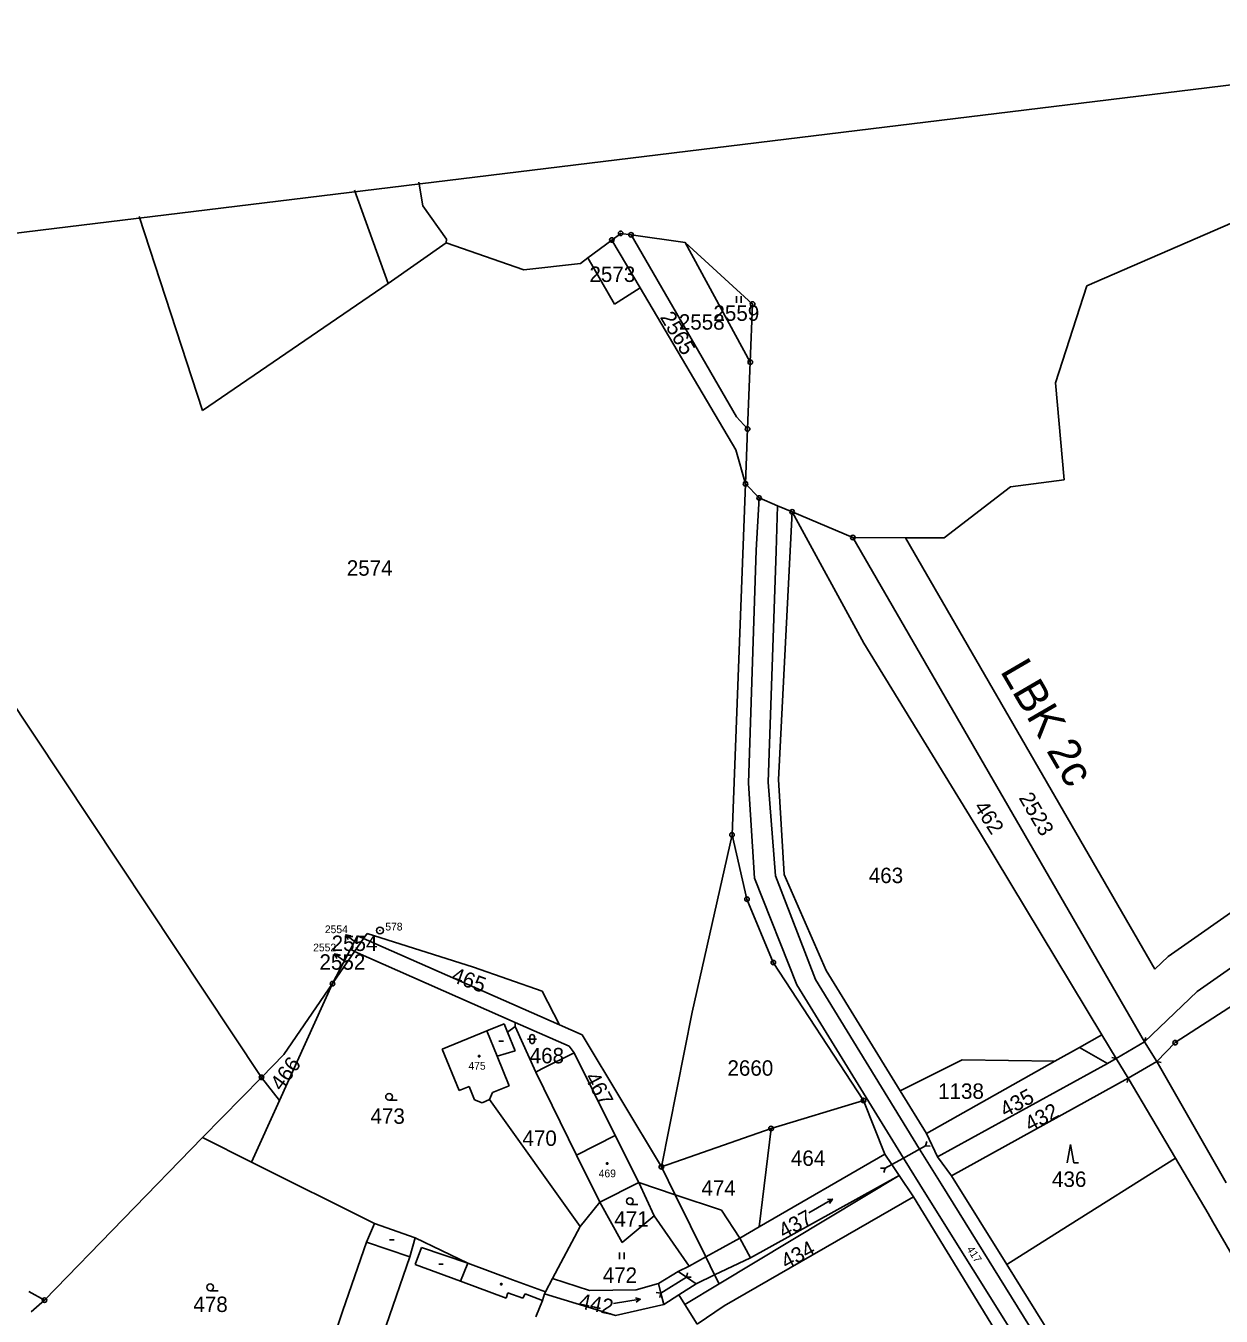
# Model space of a CAD drawing. Extents: x -567356 to -566716, y -1096092 to -1095603.
# Drawn here: x -567139.2 to -566875.4, y -1095888 to -1095603.4 of the extents above; entities that cross this region are included whole.
import ezdxf

# ---------------------------------------------------------------- set-up
doc = ezdxf.new("R2010")
doc.units = 0
for name, color, linetype in [('Vrstva 1', 7, 'Continuous'), ('Vrstva 13', 7, 'Continuous'), ('Vrstva 16', 7, 'Continuous'), ('Vrstva 17', 7, 'Continuous'), ('Vrstva 18', 7, 'Continuous'), ('Vrstva 19', 7, 'Continuous'), ('Vrstva 24', 7, 'Continuous'), ('Vrstva 25', 7, 'Continuous'), ('Vrstva 26', 7, 'Continuous'), ('Vrstva 4', 7, 'Continuous'), ('Vrstva 63', 7, 'Continuous')]:
    doc.layers.add(name, color=color, linetype=linetype)

msp = doc.modelspace()

# ---------------------------------------------------------------- linework, layer by layer
at = {"layer": 'Vrstva 1'}
for p, q in [((-567066.6, -1095639.66), (-567059.23, -1095660.29)), ((-567100.15, -1095688.25), (-567114.18, -1095645.47)), ((-567059.23, -1095660.29), (-567046.37, -1095651.29)), ((-567009.85, -1095650.68), (-567003.61, -1095661.22)), ((-567005.6, -1095649.54), (-566982.33, -1095689.66)), ((-566993.69, -1095651.22), (-566979.3, -1095677.61)), ((-567009.23, -1095664.84), (-567015.12, -1095654.61)), ((-567100.15, -1095688.25), (-567059.23, -1095660.29)), ((-567009.23, -1095664.84), (-567003.61, -1095661.22)), ((-567003.61, -1095661.22), (-566982.47, -1095696.92)), ((-566979.89, -1095692.34), (-566982.33, -1095689.66)), ((-566980.36, -1095704.46), (-566982.47, -1095696.92)), ((-566983.33, -1095781.86), (-566980.36, -1095704.46)), ((-566973.07, -1095769.68), (-566970.06, -1095710.63)), ((-566970.06, -1095710.63), (-566954.26, -1095739.57)), ((-566956.66, -1095716.28), (-566892.27, -1095827.53)), ((-566945.07, -1095716.34), (-566890.01, -1095811.47)), ((-566954.26, -1095739.57), (-566928.71, -1095781.18)), ((-567143.71, -1095750.26), (-567087.17, -1095835.34)), ((-566973.07, -1095769.68), (-566971.83, -1095790.57)), ((-566983.33, -1095781.86), (-566992.13, -1095820.96)), ((-566983.33, -1095781.86), (-566980.03, -1095796.03)), ((-566928.71, -1095781.18), (-566901.69, -1095825.95)), ((-566971.83, -1095790.57), (-566962.54, -1095811.81)), ((-566887.09, -1095808.66), (-566860.75, -1095790.2)), ((-566980.03, -1095796.03), (-566974.22, -1095810)), ((-566853.9, -1095797.61), (-566880.71, -1095816.4)), ((-567065.98, -1095804.1), (-567067.51, -1095807.04)), ((-567066.61, -1095807.58), (-567064.62, -1095804.7)), ((-567064.62, -1095804.7), (-567065.98, -1095804.1)), ((-567064.62, -1095804.7), (-567063.86, -1095803.59)), ((-567064.62, -1095804.7), (-567021.38, -1095823.77)), ((-567063.86, -1095803.59), (-567040.36, -1095811.06)), ((-567071.48, -1095814.67), (-567067.51, -1095807.04)), ((-567071.48, -1095814.67), (-567066.61, -1095807.58)), ((-567067.51, -1095807.04), (-567066.61, -1095807.58)), ((-567066.61, -1095807.58), (-567031.18, -1095823.21)), ((-566974.22, -1095810), (-566954.33, -1095840.45)), ((-566890.01, -1095811.47), (-566887.09, -1095808.66)), ((-567040.36, -1095811.06), (-567025.2, -1095816.33)), ((-566962.54, -1095811.81), (-566946.25, -1095838.28)), ((-567083.18, -1095840.45), (-567071.48, -1095814.67)), ((-567082.21, -1095830.27), (-567071.48, -1095814.67)), ((-567025.2, -1095816.33), (-567021.38, -1095823.77)), ((-566885.55, -1095827.69), (-566865.42, -1095814.66)), ((-566880.71, -1095816.4), (-566892.27, -1095827.53)), ((-566992.13, -1095820.96), (-566998.91, -1095855.06)), ((-567037.43, -1095825.1), (-567033.59, -1095823.53)), ((-567033.59, -1095823.53), (-567032.85, -1095825.38)), ((-567032.85, -1095825.38), (-567031.19, -1095824.09)), ((-567031.19, -1095824.09), (-567031.18, -1095823.21)), ((-567031.19, -1095824.09), (-567026.62, -1095834.18)), ((-567031.18, -1095823.21), (-567019.28, -1095828.45)), ((-567021.38, -1095823.77), (-567016.38, -1095825.97)), ((-567047.3, -1095829.12), (-567037.43, -1095825.1)), ((-567032.85, -1095825.38), (-567031.21, -1095829.51)), ((-567016.38, -1095825.97), (-566998.91, -1095855.06)), ((-566901.69, -1095825.95), (-566898.55, -1095831.15)), ((-566898.55, -1095831.15), (-566892.27, -1095827.53)), ((-566892.27, -1095827.53), (-566889.61, -1095831.87)), ((-566889.61, -1095831.87), (-566885.55, -1095827.69)), ((-567087.17, -1095835.34), (-567082.21, -1095830.27)), ((-567047.3, -1095829.12), (-567043.57, -1095838.27)), ((-567035.17, -1095830.65), (-567031.21, -1095829.51)), ((-567025.26, -1095833.48), (-567018.19, -1095829.96)), ((-567019.28, -1095828.45), (-567018.19, -1095829.96)), ((-567018.19, -1095829.96), (-567009.08, -1095848.19)), ((-566912.09, -1095831.8), (-566906.65, -1095828.74)), ((-566906.65, -1095828.74), (-566900.49, -1095832.28)), ((-567035.17, -1095830.65), (-567032.5, -1095837.19)), ((-566946.25, -1095838.28), (-566932.56, -1095831.46)), ((-566940.43, -1095847.73), (-566912.09, -1095831.8)), ((-566938, -1095852.89), (-566900.49, -1095832.28)), ((-566932.56, -1095831.46), (-566912.09, -1095831.8)), ((-566900.49, -1095832.28), (-566898.55, -1095831.15)), ((-566895.9, -1095835.52), (-566889.61, -1095831.87)), ((-566889.61, -1095831.87), (-566889.02, -1095832.89)), ((-566889.02, -1095832.89), (-566874.28, -1095858.61)), ((-567087.17, -1095835.34), (-567083.18, -1095840.45)), ((-567026.62, -1095834.18), (-567025.26, -1095833.48)), ((-567026.62, -1095834.18), (-567017.62, -1095852.49)), ((-566934.88, -1095857.04), (-566895.9, -1095835.52)), ((-566895.9, -1095835.52), (-566885.48, -1095853.18)), ((-567043.57, -1095838.27), (-567041.36, -1095837.37)), ((-567041.36, -1095837.37), (-567040.14, -1095840.32)), ((-567036.84, -1095840.26), (-567036.15, -1095838.68)), ((-567036.15, -1095838.68), (-567032.5, -1095837.19)), ((-566946.25, -1095838.28), (-566940.43, -1095847.73)), ((-567089.34, -1095854.03), (-567083.18, -1095840.45)), ((-567040.14, -1095840.32), (-567038.49, -1095840.93)), ((-567038.49, -1095840.93), (-567036.84, -1095840.26)), ((-567036.84, -1095840.26), (-567016.81, -1095868.27)), ((-566974.71, -1095846.61), (-566954.33, -1095840.45)), ((-566954.33, -1095840.45), (-566949.63, -1095852.31)), ((-566998.91, -1095855.06), (-566974.71, -1095846.61)), ((-566977.35, -1095868.33), (-566974.71, -1095846.61)), ((-567135.05, -1095884.49), (-567100.18, -1095848.6)), ((-567100.18, -1095848.6), (-567089.34, -1095854.03)), ((-567009.08, -1095848.19), (-567003.91, -1095858.56)), ((-566940.43, -1095847.73), (-566938, -1095852.89)), ((-567017.62, -1095852.49), (-567012.49, -1095862.9)), ((-566977.35, -1095868.33), (-566949.63, -1095852.31)), ((-566949.63, -1095852.31), (-566948.07, -1095854.58)), ((-566938, -1095852.89), (-566934.88, -1095857.04)), ((-566910.71, -1095869.05), (-566885.48, -1095853.18)), ((-566885.48, -1095853.18), (-566878.27, -1095865.39)), ((-567089.34, -1095854.03), (-567062.24, -1095867.59)), ((-566998.91, -1095855.06), (-566995.87, -1095861.24)), ((-566948.07, -1095854.58), (-566946.44, -1095856.96)), ((-567012.49, -1095862.9), (-567003.91, -1095858.56)), ((-567003.91, -1095858.56), (-567000.49, -1095865.9)), ((-566986.19, -1095880.91), (-566946.44, -1095856.96)), ((-566946.44, -1095856.96), (-566943.29, -1095861.67)), ((-566934.88, -1095857.04), (-566922.69, -1095876.58)), ((-566995.87, -1095861.24), (-566989.12, -1095874.96)), ((-566985.06, -1095885.7), (-566943.29, -1095861.67)), ((-566943.29, -1095861.67), (-566884.03, -1095958.24)), ((-567016.81, -1095868.27), (-567012.49, -1095862.9)), ((-567012.49, -1095862.9), (-567007.55, -1095871.78)), ((-567063.98, -1095871.66), (-567062.24, -1095867.59)), ((-567062.24, -1095867.59), (-567053.28, -1095870.73)), ((-567007.55, -1095871.78), (-567000.49, -1095865.9)), ((-567000.49, -1095865.9), (-566992.8, -1095877)), ((-566878.27, -1095865.39), (-566877.22, -1095867.21)), ((-566877.22, -1095867.21), (-566842.91, -1095926.64)), ((-567022.92, -1095879.69), (-567016.81, -1095868.27)), ((-566981.59, -1095870.78), (-566977.35, -1095868.33)), ((-566922.69, -1095876.58), (-566910.71, -1095869.05)), ((-567069.18, -1095886.79), (-567063.98, -1095871.66)), ((-567063.98, -1095871.66), (-567054.4, -1095874.96)), ((-567053.28, -1095870.73), (-567041.66, -1095876.31)), ((-566989.12, -1095874.96), (-566981.59, -1095870.78)), ((-567059.63, -1095890.09), (-567054.4, -1095874.96)), ((-566989.12, -1095874.96), (-566987.17, -1095878.92)), ((-567041.66, -1095876.31), (-567031.77, -1095880)), ((-566999.58, -1095880.79), (-566995.2, -1095878.17)), ((-566995.2, -1095878.17), (-566992.8, -1095877)), ((-566995.2, -1095878.17), (-566993.37, -1095879.4)), ((-566987.17, -1095878.92), (-566986.19, -1095880.91)), ((-566922.69, -1095876.58), (-566875.46, -1095952.32)), ((-567031.77, -1095880), (-567024.52, -1095882.64)), ((-567024.52, -1095882.64), (-567022.92, -1095879.69)), ((-567022.92, -1095879.69), (-567014.77, -1095882.35)), ((-567004.5, -1095882.17), (-566999.58, -1095880.79)), ((-566995.04, -1095883.32), (-566991.21, -1095880.86)), ((-566993.71, -1095885.45), (-566986.19, -1095880.91)), ((-566993.37, -1095879.4), (-566991.21, -1095880.86)), ((-567138.51, -1095882.55), (-567135.05, -1095884.49)), ((-567137.96, -1095887.08), (-567135.05, -1095884.49)), ((-567026.61, -1095888.14), (-567025.14, -1095884.52)), ((-567025.14, -1095884.52), (-567024.67, -1095883.12)), ((-567024.67, -1095883.12), (-567024.52, -1095882.64)), ((-567024.67, -1095883.12), (-567009.06, -1095887.89)), ((-567014.77, -1095882.35), (-567009.64, -1095882.27)), ((-567009.64, -1095882.27), (-567004.5, -1095882.17)), ((-566998.39, -1095885.47), (-566995.04, -1095883.32)), ((-566995.04, -1095883.32), (-566993.71, -1095885.45)), ((-567077.17, -1095910.04), (-567069.18, -1095886.79)), ((-567009.06, -1095887.89), (-566998.39, -1095885.47)), ((-566993.71, -1095885.45), (-566991.03, -1095889.76)), ((-566991.03, -1095889.76), (-566985.06, -1095885.7))]:
    msp.add_line(p, q, dxfattribs=at)
at = {"layer": 'Vrstva 13'}
for p, q in [((-566905.05, -1095660.75), (-566817.77, -1095622.91)), ((-567052.47, -1095637.93), (-567051.59, -1095643.13)), ((-567051.59, -1095643.13), (-567046.33, -1095650.51)), ((-567046.33, -1095650.51), (-567046.37, -1095651.29)), ((-567046.37, -1095651.29), (-567029.28, -1095657.25)), ((-567015.12, -1095654.61), (-567009.85, -1095650.68)), ((-567009.85, -1095650.68), (-567007.89, -1095649.21)), ((-567007.89, -1095649.21), (-567005.6, -1095649.54)), ((-567005.6, -1095649.54), (-566993.69, -1095651.22)), ((-566993.69, -1095651.22), (-566978.79, -1095664.8)), ((-567029.28, -1095657.25), (-567016.78, -1095655.85)), ((-567016.78, -1095655.85), (-567015.12, -1095654.61)), ((-566911.94, -1095682.15), (-566905.05, -1095660.75)), ((-566978.79, -1095664.8), (-566979.3, -1095677.61)), ((-566979.3, -1095677.61), (-566979.89, -1095692.34)), ((-566910.02, -1095703.54), (-566911.94, -1095682.15)), ((-566979.89, -1095692.34), (-566980.36, -1095704.46)), ((-566980.36, -1095704.46), (-566977.35, -1095707.56)), ((-566936.49, -1095716.38), (-566921.91, -1095705.12)), ((-566921.91, -1095705.12), (-566910.02, -1095703.54)), ((-566977.35, -1095707.56), (-566973.27, -1095709.28)), ((-566973.27, -1095709.28), (-566970.06, -1095710.63)), ((-566970.06, -1095710.63), (-566956.66, -1095716.28)), ((-566956.66, -1095716.28), (-566945.07, -1095716.34)), ((-566945.07, -1095716.34), (-566936.49, -1095716.38))]:
    msp.add_line(p, q, dxfattribs=at)
at = {"layer": 'Vrstva 16'}
for p, q in [((-567066.15, -1095805.71), (-567068.57, -1095803.94)), ((-567068.6, -1095809.9), (-567071.02, -1095808.13))]:
    msp.add_line(p, q, dxfattribs=at)
for points in [[(-567068.06, -1095804.94), (-567068.57, -1095803.94), (-567067.47, -1095804.13)], [(-567070.51, -1095809.13), (-567071.02, -1095808.13), (-567069.92, -1095808.32)]]:
    msp.add_lwpolyline(points, dxfattribs=at)
at = {"layer": 'Vrstva 24'}
for centre, radius in [((-567009.85, -1095650.68), 0.5), ((-567009.85, -1095650.68), 0.0327), ((-567007.89, -1095649.21), 0.5), ((-567007.89, -1095649.21), 0.0327), ((-567005.6, -1095649.54), 0.5), ((-567005.6, -1095649.54), 0.0327), ((-566978.79, -1095664.8), 0.5), ((-566978.79, -1095664.8), 0.0327), ((-566979.3, -1095677.61), 0.5), ((-566979.3, -1095677.61), 0.0327), ((-566979.89, -1095692.34), 0.5), ((-566979.89, -1095692.34), 0.0327), ((-566980.36, -1095704.46), 0.5), ((-566980.36, -1095704.46), 0.0327), ((-566977.35, -1095707.56), 0.5), ((-566977.35, -1095707.56), 0.0327), ((-566970.06, -1095710.63), 0.5), ((-566970.06, -1095710.63), 0.0327), ((-566956.66, -1095716.28), 0.5), ((-566956.66, -1095716.28), 0.0327), ((-566983.33, -1095781.86), 0.5), ((-566983.33, -1095781.86), 0.5), ((-566983.33, -1095781.86), 0.0327), ((-566983.33, -1095781.86), 0.0327), ((-566980.03, -1095796.03), 0.5), ((-566980.03, -1095796.03), 0.5), ((-566980.03, -1095796.03), 0.0327), ((-566980.03, -1095796.03), 0.0327), ((-567061.02, -1095802.96), 0.75), ((-567061.02, -1095802.96), 0.0327), ((-566974.22, -1095810), 0.5), ((-566974.22, -1095810), 0.5), ((-566974.22, -1095810), 0.0327), ((-566974.22, -1095810), 0.0327), ((-567071.48, -1095814.67), 0.5), ((-567071.48, -1095814.67), 0.5), ((-567071.48, -1095814.67), 0.0327), ((-567071.48, -1095814.67), 0.0327), ((-566885.55, -1095827.69), 0.5), ((-566885.55, -1095827.69), 0.5), ((-566885.55, -1095827.69), 0.0327), ((-566885.55, -1095827.69), 0.0327), ((-567087.17, -1095835.34), 0.5), ((-567087.17, -1095835.34), 0.5), ((-567087.17, -1095835.34), 0.0327), ((-567087.17, -1095835.34), 0.0327), ((-566954.33, -1095840.45), 0.5), ((-566954.33, -1095840.45), 0.5), ((-566954.33, -1095840.45), 0.0327), ((-566954.33, -1095840.45), 0.0327), ((-566974.71, -1095846.61), 0.5), ((-566974.71, -1095846.61), 0.5), ((-566974.71, -1095846.61), 0.0327), ((-566974.71, -1095846.61), 0.0327), ((-566998.91, -1095855.06), 0.5), ((-566998.91, -1095855.06), 0.5), ((-566998.91, -1095855.06), 0.0327), ((-566998.91, -1095855.06), 0.0327), ((-567135.05, -1095884.49), 0.5), ((-567135.05, -1095884.49), 0.0327)]:
    msp.add_circle(centre, radius, dxfattribs=at)
at = {"layer": 'Vrstva 25'}
for p, q in [((-566982.33, -1095663.06), (-566982.33, -1095664.56)), ((-566981.31, -1095664.56), (-566981.31, -1095663.06)), ((-567034.77, -1095827.37), (-567033.77, -1095827.37)), ((-567028.44, -1095826.89), (-567026.44, -1095826.89)), ((-567027.94, -1095827.39), (-567027.94, -1095826.39)), ((-567026.94, -1095827.39), (-567026.94, -1095826.39)), ((-567057.25, -1095840.38), (-567059, -1095840.38)), ((-566908.63, -1095850.18), (-566909.36, -1095854.18)), ((-566908.63, -1095850.18), (-566907.9, -1095854.18)), ((-566907.9, -1095854.18), (-566906.9, -1095854.18)), ((-567004.12, -1095863.39), (-567005.87, -1095863.39)), ((-566966.35, -1095865.24), (-566961.17, -1095862.2)), ((-567058.88, -1095871.17), (-567057.88, -1095871.17)), ((-567008.14, -1095873.94), (-567008.14, -1095875.44)), ((-567007.11, -1095875.44), (-567007.11, -1095873.94)), ((-567048.06, -1095876.56), (-567047.06, -1095876.56)), ((-567096.73, -1095882.39), (-567098.48, -1095882.39)), ((-567009.49, -1095885.23), (-567003.57, -1095884.27))]:
    msp.add_line(p, q, dxfattribs=at)
for points in [[(-566962.29, -1095862.28), (-566961.17, -1095862.2), (-566961.78, -1095863.14)], [(-567004.63, -1095883.94), (-567003.57, -1095884.27), (-567004.48, -1095884.93)]]:
    msp.add_lwpolyline(points, dxfattribs=at)
for centre, radius in [((-567039.13, -1095830.67), 0.175), ((-567059, -1095839.63), 0.75), ((-567010.87, -1095854.34), 0.175), ((-567005.87, -1095862.64), 0.75), ((-567098.48, -1095881.64), 0.75), ((-567034.25, -1095880.95), 0.175)]:
    msp.add_circle(centre, radius, dxfattribs=at)
for centre, start, end in [((-567027.44, -1095826.39), 0, 180), ((-567027.44, -1095827.39), 180, 0)]:
    msp.add_arc(centre, 0.5, start, end, dxfattribs=at)
at = {"layer": 'Vrstva 26'}
for p, q in [((-566892.03, -1095826.56), (-566892.27, -1095827.53)), ((-566899.53, -1095830.97), (-566898.55, -1095831.15)), ((-566888.63, -1095832.06), (-566889.61, -1095831.87)), ((-566896.15, -1095836.49), (-566895.9, -1095835.52)), ((-566940.36, -1095849.47), (-566940.63, -1095850.43)), ((-566939.63, -1095850.52), (-566940.63, -1095850.43)), ((-566950.55, -1095855.39), (-566949.55, -1095855.4)), ((-566949.82, -1095856.36), (-566949.55, -1095855.4)), ((-566993.12, -1095878.43), (-566993.37, -1095879.4)), ((-566992.37, -1095879.43), (-566993.37, -1095879.4)), ((-567000.03, -1095882.8), (-566999.04, -1095882.93)), ((-566999.27, -1095883.9), (-566999.04, -1095882.93))]:
    msp.add_line(p, q, dxfattribs=at)
at = {"layer": 'Vrstva 4'}
for p, q in [((-566978.02, -1095719.05), (-566977.35, -1095707.56)), ((-566973.62, -1095719.3), (-566973.27, -1095709.28)), ((-566979.66, -1095770.48), (-566978.02, -1095719.05)), ((-566975.37, -1095770.22), (-566973.62, -1095719.3)), ((-566978.35, -1095791.42), (-566979.66, -1095770.48)), ((-566975.37, -1095770.22), (-566973.73, -1095790.93)), ((-566978.35, -1095791.42), (-566969.06, -1095814.95)), ((-566973.73, -1095790.93), (-566964.88, -1095813.78)), ((-566969.06, -1095814.95), (-566945.5, -1095853.14)), ((-566964.88, -1095813.78), (-566941.92, -1095851.15)), ((-567037.43, -1095825.1), (-567035.17, -1095830.65)), ((-566906.65, -1095828.74), (-566901.69, -1095825.95)), ((-566898.55, -1095831.15), (-566895.9, -1095835.52)), ((-567100.18, -1095848.6), (-567087.17, -1095835.34)), ((-567017.62, -1095852.49), (-567009.08, -1095848.19)), ((-566941.92, -1095851.15), (-566940.63, -1095850.43)), ((-566948.07, -1095854.58), (-566945.5, -1095853.14)), ((-566945.5, -1095853.14), (-566941.92, -1095851.15)), ((-566945.5, -1095853.14), (-566940.59, -1095861.1)), ((-566941.92, -1095851.15), (-566937.2, -1095858.82)), ((-566949.55, -1095855.4), (-566948.07, -1095854.58)), ((-567003.91, -1095858.56), (-566995.87, -1095861.24)), ((-566979.27, -1095875.11), (-566946.44, -1095856.96)), ((-566937.2, -1095858.82), (-566877.93, -1095954.2)), ((-566995.87, -1095861.24), (-566985.63, -1095864.65)), ((-566940.59, -1095861.1), (-566881.1, -1095956.07)), ((-566985.63, -1095864.65), (-566981.59, -1095870.78)), ((-567054.4, -1095874.96), (-567053.28, -1095870.73)), ((-567053.25, -1095876.59), (-567051.82, -1095872.86)), ((-567051.82, -1095872.86), (-567041.66, -1095876.31)), ((-566981.59, -1095870.78), (-566979.27, -1095875.11)), ((-566992.8, -1095877), (-566989.12, -1095874.96)), ((-566987.17, -1095878.92), (-566979.27, -1095875.11)), ((-567053.25, -1095876.59), (-567043.26, -1095880.29)), ((-567043.26, -1095880.29), (-567041.66, -1095876.31)), ((-566991.21, -1095880.86), (-566987.17, -1095878.92)), ((-567043.26, -1095880.29), (-567033.17, -1095884.06)), ((-566999.58, -1095880.79), (-566999.04, -1095882.93)), ((-566999.04, -1095882.93), (-566993.37, -1095879.4)), ((-567033.17, -1095884.06), (-567032.77, -1095882.88)), ((-567032.77, -1095882.88), (-567029.48, -1095884.07)), ((-567029.48, -1095884.07), (-567028.97, -1095883.07)), ((-567028.97, -1095883.07), (-567025.14, -1095884.52)), ((-566999.04, -1095882.93), (-566998.39, -1095885.47))]:
    msp.add_line(p, q, dxfattribs=at)
at = {"layer": 'Vrstva 63'}
msp.add_line((-567356.16, -1095675.38), (-566766.53, -1095603.43), dxfattribs=at)

# ---------------------------------------------------------------- texts
at = {"layer": 'Vrstva 1'}
msp.add_text('LBK 2c', height=7, rotation=300.2227, dxfattribs=at).set_placement((-566924.27, -1095745.73))
at = {"layer": 'Vrstva 16'}
for s, p in [('2554', (-567073.17, -1095803.54)), ('2552', (-567075.75, -1095807.55))]:
    msp.add_text(s, height=1.7, dxfattribs=at).set_placement(p)
msp.add_text('417', height=1.7, rotation=302.922, dxfattribs=at).set_placement((-566931.61, -1095873.22))
at = {"layer": 'Vrstva 17'}
msp.add_text('578', height=1.7, dxfattribs=at).set_placement((-567059.83, -1095802.95))
at = {"layer": 'Vrstva 18'}
for s, p in [('2573', (-567014.79, -1095659.92)), ('2559', (-566987.43, -1095668.5)), ('2558', (-566995.07, -1095670.44)), ('2574', (-567068.34, -1095724.7)), ('463', (-566953.15, -1095792.5)), ('2554', (-567071.68, -1095807.47)), ('2552', (-567074.37, -1095811.6)), ('468', (-567027.98, -1095832.25)), ('2660', (-566984.34, -1095834.98)), ('1138', (-566937.86, -1095840.08)), ('473', (-567063.11, -1095845.59)), ('470', (-567029.58, -1095850.46)), ('464', (-566970.34, -1095854.86)), ('436', (-566912.72, -1095859.5)), ('474', (-566990.09, -1095861.47)), ('471', (-567009.3, -1095868.27)), ('472', (-567011.86, -1095880.66)), ('478', (-567102.19, -1095887.09))]:
    msp.add_text(s, height=3.4, dxfattribs=at).set_placement(p)
for s, rotation, p in [('2565', 300.6, (-566999.32, -1095667.68)), ('2523', 300.1742, (-566920.14, -1095773.69)), ('462', 302.634, (-566930.09, -1095775.69)), ('465', 339.939, (-567045.52, -1095814.15)), ('466', 53.973, (-567082.74, -1095838.54)), ('467', 298.224, (-567015.93, -1095835.32)), ('435', 28.188, (-566923.03, -1095844.23)), ('432', 28.188, (-566917.56, -1095847.42)), ('437', 28.647, (-566971.89, -1095871)), ('434', 27.675, (-566971.39, -1095877.72)), ('442', 348.534, (-567017.35, -1095886.24))]:
    msp.add_text(s, height=3.4, rotation=rotation, dxfattribs=at).set_placement(p)
at = {"layer": 'Vrstva 19'}
for s, p in [('475', (-567041.49, -1095833.65)), ('469', (-567012.74, -1095857.38))]:
    msp.add_text(s, height=1.7, dxfattribs=at).set_placement(p)

doc.saveas('drawing.dxf')
